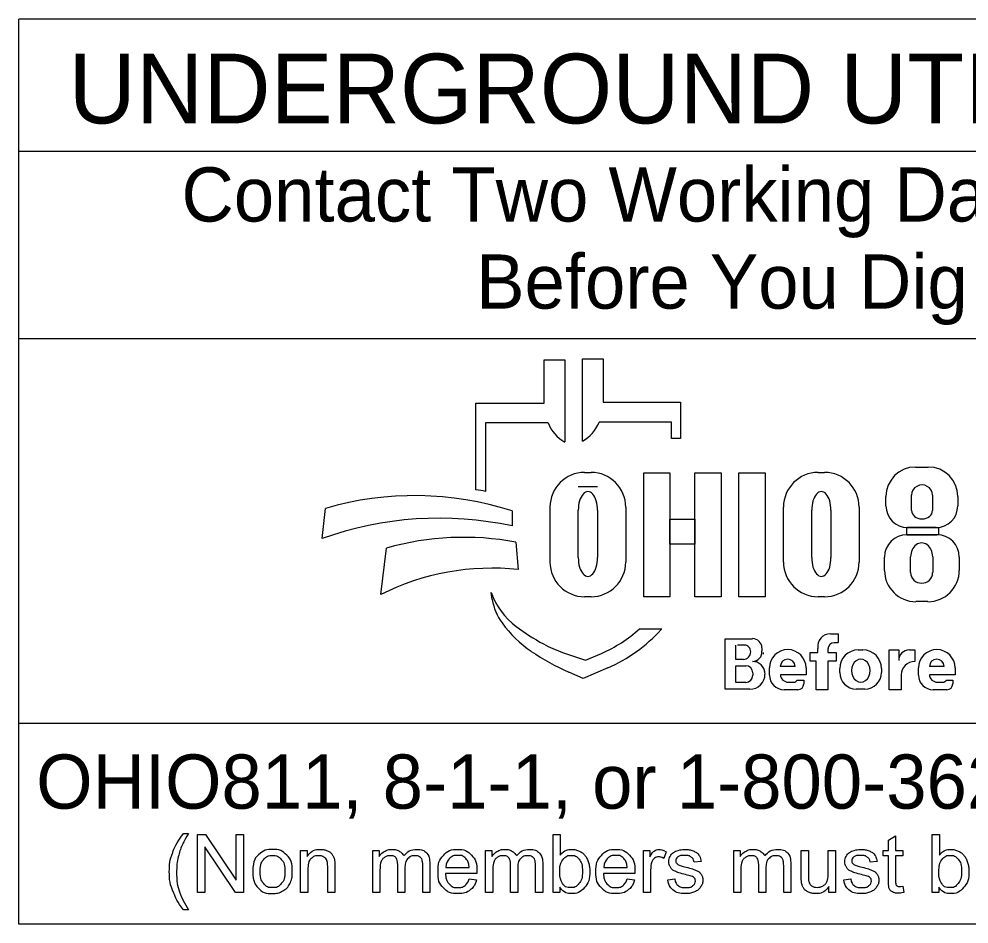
# Model space of a CAD drawing. Extents: x 5.6 to 39.6, y 0.7 to 22.7.
# Drawn here: x 13.593 to 16.047, y 9.658 to 11.996 of the extents above; entities that cross this region are included whole.
import ezdxf

# ---------------------------------------------------------------- set-up
doc = ezdxf.new("R2010")
doc.units = 0
doc.layers.add('SH_Data', color=7, linetype='Continuous')
doc.layers.add('SH_Text', color=7, linetype='Continuous')

msp = doc.modelspace()

# ---------------------------------------------------------------- linework, layer by layer
at = {"layer": 'SH_Data'}
for p, q in [((13.5934, 9.6584), (13.5934, 11.9959)), ((17.8434, 11.9959), (13.5934, 11.9959)), ((13.5934, 11.6544), (17.8434, 11.6544)), ((13.5934, 11.171), (17.8434, 11.171)), ((17.8434, 10.1763), (13.5934, 10.1763)), ((17.8434, 9.6584), (13.5934, 9.6584))]:
    msp.add_line(p, q, dxfattribs=at)
at = {"layer": 'SH_Text'}
for p, q in [((15.0488, 10.9057), (15.0488, 11.1178)), ((15.0488, 11.1178), (15.1024, 11.1178)), ((15.1024, 11.1178), (15.1024, 11.0063)), ((14.9495, 11.004), (14.9495, 11.1154)), ((14.9495, 11.1154), (15.0031, 11.1154)), ((15.0031, 11.1154), (15.0031, 10.9034)), ((14.7735, 10.7801), (14.7735, 11.004)), ((14.7735, 11.004), (14.9495, 11.004)), ((15.1024, 11.0063), (15.3017, 11.0063)), ((15.3017, 11.0063), (15.3017, 10.9125)), ((14.7987, 10.9525), (14.7987, 10.7757)), ((14.9599, 10.9525), (14.7987, 10.9525)), ((15.2784, 10.9548), (15.092, 10.9548)), ((15.2784, 10.9125), (15.2784, 10.9548)), ((15.3017, 10.9125), (15.2784, 10.9125)), ((15.0544, 10.8248), (15.071, 10.8248)), ((15.6575, 10.8248), (15.674, 10.8248)), ((15.909, 10.8388), (15.9418, 10.8388)), ((15.0877, 10.7878), (15.0379, 10.7878)), ((15.8327, 10.7382), (15.8327, 10.7625)), ((15.8989, 10.7268), (15.8989, 10.7661)), ((15.953, 10.7661), (15.953, 10.7268)), ((16.0181, 10.7625), (16.0181, 10.7382)), ((14.3761, 10.6538), (14.3855, 10.7319)), ((14.8668, 10.7254), (14.8668, 10.6866)), ((14.965, 10.5933), (14.965, 10.7353)), ((15.0379, 10.6047), (15.0379, 10.727)), ((15.0877, 10.727), (15.0877, 10.6047)), ((15.1605, 10.7353), (15.1605, 10.5933)), ((15.568, 10.5933), (15.568, 10.7353)), ((15.6409, 10.6047), (15.6409, 10.727)), ((15.6907, 10.727), (15.6907, 10.6047)), ((15.7635, 10.7353), (15.7635, 10.5933)), ((15.9621, 10.6822), (15.8887, 10.6822)), ((15.8869, 10.6639), (15.9642, 10.6639)), ((14.528, 10.5092), (14.5426, 10.6294)), ((14.8768, 10.6448), (14.883, 10.5738)), ((15.829, 10.5719), (15.829, 10.606)), ((15.8965, 10.566), (15.8965, 10.6069)), ((15.9534, 10.6069), (15.9534, 10.566)), ((16.0221, 10.606), (16.0221, 10.5719)), ((14.8157, 10.4963), (14.8126, 10.5143)), ((15.071, 10.5038), (15.0544, 10.5038)), ((15.674, 10.5038), (15.6575, 10.5038)), ((15.9412, 10.491), (15.91, 10.491)), ((15.1959, 10.4205), (15.2534, 10.4205)), ((15.6898, 10.4082), (15.7093, 10.4082)), ((15.7093, 10.4082), (15.7093, 10.3852)), ((15.4172, 10.2647), (15.4172, 10.3954)), ((15.4172, 10.3954), (15.4884, 10.3954)), ((15.7093, 10.3848), (15.6991, 10.3848)), ((14.9975, 10.3601), (15.0569, 10.3396)), ((15.0569, 10.3396), (15.098, 10.3574)), ((15.4452, 10.3419), (15.4452, 10.3789)), ((15.4704, 10.3789), (15.4491, 10.3789)), ((15.5122, 10.3717), (15.5122, 10.3638)), ((15.6372, 10.3369), (15.6372, 10.3598)), ((15.6372, 10.3598), (15.6565, 10.3598)), ((15.6565, 10.3598), (15.6565, 10.3703)), ((15.6826, 10.3683), (15.6826, 10.3598)), ((15.6826, 10.3598), (15.7042, 10.3598)), ((15.7042, 10.3598), (15.7042, 10.3369)), ((15.761, 10.3664), (15.7732, 10.3664)), ((15.8413, 10.2635), (15.8413, 10.3662)), ((15.8413, 10.3662), (15.8658, 10.3662)), ((15.8658, 10.3662), (15.8658, 10.3393)), ((15.8931, 10.3662), (15.907, 10.3662)), ((15.907, 10.3662), (15.907, 10.3365)), ((15.4646, 10.3419), (15.4452, 10.3419)), ((15.6521, 10.3369), (15.6372, 10.3369)), ((15.6521, 10.2635), (15.6521, 10.3369)), ((15.7042, 10.3369), (15.6826, 10.3369)), ((15.6826, 10.3369), (15.6826, 10.2635)), ((15.0509, 10.2926), (15.0136, 10.309)), ((15.1142, 10.32), (15.0509, 10.2926)), ((15.4452, 10.2825), (15.4452, 10.3254)), ((15.4452, 10.3254), (15.4707, 10.3254)), ((15.4889, 10.3073), (15.4889, 10.3009)), ((15.5318, 10.3015), (15.5318, 10.3199)), ((15.5984, 10.3239), (15.5598, 10.3239)), ((15.6263, 10.3199), (15.6263, 10.3022)), ((15.7132, 10.3078), (15.7132, 10.3186)), ((15.821, 10.3186), (15.821, 10.3078)), ((15.9167, 10.3015), (15.9167, 10.3199)), ((15.9833, 10.3239), (15.9448, 10.3239)), ((16.0112, 10.3199), (16.0112, 10.3022)), ((15.4705, 10.2825), (15.4452, 10.2825)), ((15.5202, 10.3044), (15.5202, 10.304)), ((15.6263, 10.3022), (15.5599, 10.3022)), ((15.5808, 10.283), (15.5949, 10.283)), ((15.6035, 10.2885), (15.6204, 10.2885)), ((15.6204, 10.2885), (15.6204, 10.2787)), ((15.8718, 10.3016), (15.8718, 10.2635)), ((16.0112, 10.3022), (15.9448, 10.3022)), ((15.9657, 10.283), (15.9799, 10.283)), ((15.9884, 10.2885), (16.0053, 10.2885)), ((16.0053, 10.2885), (16.0053, 10.2787)), ((15.4809, 10.2647), (15.4172, 10.2647)), ((15.6051, 10.2635), (15.5698, 10.2635)), ((15.6826, 10.2635), (15.6521, 10.2635)), ((15.7782, 10.265), (15.756, 10.265)), ((15.8718, 10.2635), (15.8413, 10.2635)), ((15.9901, 10.2635), (15.9547, 10.2635))]:
    msp.add_line(p, q, dxfattribs=at)
for points in [[(15.2069, 10.8237), (15.2748, 10.8237), (15.2748, 10.5037), (15.2069, 10.5037)], [(15.339, 10.8237), (15.407, 10.8237), (15.407, 10.5037), (15.339, 10.5037)], [(15.4523, 10.8237), (15.5211, 10.8237), (15.5211, 10.5037), (15.4523, 10.5037)], [(15.2748, 10.7038), (15.339, 10.7038), (15.339, 10.6398), (15.2748, 10.6398)], [(15.8866, 10.6822), (15.9682, 10.6822), (15.9682, 10.6637), (15.8866, 10.6637)]]:
    msp.add_lwpolyline(points, close=True, dxfattribs=at)
for points in [[(14.018, 9.8922), (14.0312, 9.8922)], [(14.0548, 9.7396), (14.0548, 9.8897), (14.0751, 9.8897), (14.1541, 9.7718), (14.1541, 9.8897), (14.1731, 9.8897), (14.1731, 9.7396), (14.1528, 9.7396), (14.0738, 9.8575), (14.0738, 9.7396), (14.0548, 9.7396)], [(14.9902, 9.7396), (14.9732, 9.7396), (14.9732, 9.8897), (14.9916, 9.8897), (14.9916, 9.8362)], [(15.9693, 9.7396), (15.9523, 9.7396), (15.9523, 9.8897), (15.9707, 9.8897), (15.9707, 9.8362)], [(15.8392, 9.7714), (15.8392, 9.8341), (15.8256, 9.8341), (15.8256, 9.8484), (15.8392, 9.8484), (15.8392, 9.8754), (15.8576, 9.8864), (15.8576, 9.8484), (15.876, 9.8484), (15.876, 9.8341), (15.8576, 9.8341), (15.8576, 9.7703)], [(14.3207, 9.7396), (14.3207, 9.8484), (14.3373, 9.8484), (14.3373, 9.8329)], [(14.5072, 9.7396), (14.5072, 9.8484), (14.5236, 9.8484), (14.5236, 9.8331)], [(14.7985, 9.7396), (14.7985, 9.8484), (14.815, 9.8484), (14.815, 9.8331)], [(15.2063, 9.7396), (15.2063, 9.8484), (15.2229, 9.8484), (15.2229, 9.8319)], [(15.2654, 9.8449), (15.2589, 9.8279)], [(15.4395, 9.7396), (15.4395, 9.8484), (15.456, 9.8484), (15.456, 9.8331)], [(15.6138, 9.781), (15.6138, 9.8484), (15.6323, 9.8484), (15.6323, 9.7881)], [(15.6835, 9.7901), (15.6835, 9.8484), (15.702, 9.8484), (15.702, 9.7396), (15.6855, 9.7396)], [(15.3553, 9.8203), (15.3372, 9.8179)], [(15.8099, 9.8203), (15.7918, 9.8179)], [(14.3392, 9.799), (14.3392, 9.7396), (14.3207, 9.7396)], [(14.4091, 9.8065), (14.4091, 9.7396), (14.3907, 9.7396), (14.3907, 9.8057)], [(14.5256, 9.796), (14.5256, 9.7396), (14.5072, 9.7396)], [(14.5902, 9.8027), (14.5902, 9.7396), (14.5718, 9.7396), (14.5718, 9.8102)], [(14.6547, 9.8142), (14.6547, 9.7396), (14.6362, 9.7396), (14.6362, 9.8081)], [(14.6958, 9.8044), (14.7565, 9.8044)], [(14.817, 9.796), (14.817, 9.7396), (14.7985, 9.7396)], [(14.8816, 9.8027), (14.8816, 9.7396), (14.8632, 9.7396), (14.8632, 9.8102)], [(14.946, 9.8142), (14.946, 9.7396), (14.9276, 9.7396), (14.9276, 9.8081)], [(15.1038, 9.8044), (15.1645, 9.8044)], [(15.2247, 9.7966), (15.2247, 9.7396), (15.2063, 9.7396)], [(15.458, 9.796), (15.458, 9.7396), (15.4395, 9.7396)], [(15.5226, 9.8027), (15.5226, 9.7396), (15.5042, 9.7396), (15.5042, 9.8102)], [(15.587, 9.8142), (15.587, 9.7396), (15.5686, 9.7396), (15.5686, 9.8081)], [(14.7759, 9.7892), (14.6947, 9.7892)], [(14.7563, 9.7747), (14.7754, 9.7723)], [(15.1839, 9.7892), (15.1027, 9.7892)], [(15.1643, 9.7747), (15.1834, 9.7723)], [(15.2689, 9.7721), (15.2871, 9.7749)], [(15.7235, 9.7721), (15.7417, 9.7749)], [(14.9902, 9.7532), (14.9902, 9.7396)], [(15.6855, 9.7396), (15.6855, 9.7556)], [(15.876, 9.756), (15.8787, 9.7397)], [(15.9693, 9.7532), (15.9693, 9.7396)], [(14.0312, 9.6954), (14.018, 9.6954)]]:
    msp.add_lwpolyline(points, dxfattribs=at)
for centre, radius, start, end in [((15.0512, 10.9893), 0.0985, 201.9296, 240.7469), ((15.0006, 10.9916), 0.0985, 299.2531, 338.0704), ((15.0544, 10.7353), 0.0895, 90, 180), ((15.071, 10.7353), 0.0895, 0, 90), ((15.6575, 10.7353), 0.0895, 90, 180), ((15.674, 10.7353), 0.0895, 0, 90), ((15.909, 10.7625), 0.0763, 90, 180), ((15.9418, 10.7625), 0.0763, 0, 90), ((14.6454, 9.9711), 0.8191, 79.2074, 81.0007), ((14.6156, 9.9458), 0.8191, 72.1402, 106.3144), ((15.8887, 10.7382), 0.056, 180, 270), ((15.9621, 10.7382), 0.056, 270, 0), ((14.6787, 9.8147), 0.8919, 77.8238, 109.8274), ((14.7426, 9.925), 0.7322, 79.44, 105.8467), ((15.8869, 10.606), 0.0579, 90, 180), ((15.9642, 10.606), 0.0579, 0, 90), ((14.8146, 9.9418), 0.6357, 83.8248, 116.8021), ((15.0544, 10.5933), 0.0895, 180, 270), ((15.071, 10.5933), 0.0895, 270, 0), ((15.6575, 10.5933), 0.0895, 180, 270), ((15.674, 10.5933), 0.0895, 270, 0), ((15.91, 10.5719), 0.081, 180, 270), ((15.9412, 10.5719), 0.081, 270, 0), ((15, 10.5864), 0.2008, 201.0457, 232.5314), ((14.957, 10.5204), 0.1433, 189.6817, 216.0884), ((15.0906, 10.6179), 0.3088, 216.0884, 235.7167), ((15.1925, 10.8376), 0.5173, 232.5314, 241.794), ((14.9546, 10.6879), 0.3602, 293.4582, 312.0712), ((14.9546, 10.6879), 0.401, 293.4582, 317.8286), ((15.6898, 10.3747), 0.0335, 90, 187.5187), ((15.1073, 10.6788), 0.3371, 241.794, 250.9821), ((15.4884, 10.3717), 0.0238, 0, 90), ((15.6991, 10.3683), 0.0165, 90, 180), ((15.2571, 10.8621), 0.6044, 235.7167, 246.2325), ((15.4646, 10.3607), 0.0187, 270, 2.0582), ((15.4665, 10.362), 0.0169, 357.8325, 90), ((15.488, 10.3609), 0.0243, 270, 6.6529), ((15.4986, 10.3595), 0.0175, 347.4023, 0), ((15.579, 10.3199), 0.0473, 0, 180), ((15.761, 10.3186), 0.0478, 90, 180), ((15.7732, 10.3186), 0.0478, 0, 90), ((15.8927, 10.3393), 0.0269, 89.2449, 180), ((15.964, 10.3199), 0.0473, 0, 180), ((15.4881, 10.3045), 0.0321, 4.0748, 90), ((15.5791, 10.3229), 0.0193, 2.9632, 177.0368), ((15.9067, 10.3016), 0.0349, 89.6033, 180), ((15.964, 10.3229), 0.0193, 2.9632, 177.0368), ((15.4707, 10.3073), 0.0181, 0, 90), ((15.4873, 10.3044), 0.033, 0, 11.7502), ((15.756, 10.3078), 0.0428, 180, 270), ((15.7782, 10.3078), 0.0428, 270, 0), ((15.4705, 10.3009), 0.0184, 270, 0), ((15.4809, 10.304), 0.0393, 270, 0), ((15.5698, 10.3015), 0.038, 180, 270), ((15.5808, 10.304), 0.021, 184.827, 270), ((15.5949, 10.2924), 0.00938, 270, 335.9979), ((15.9547, 10.3015), 0.038, 180, 270), ((15.9657, 10.304), 0.021, 184.827, 270), ((15.9799, 10.2924), 0.00938, 270, 335.9979), ((15.6051, 10.2787), 0.0152, 270, 0), ((15.9901, 10.2787), 0.0152, 270, 0)]:
    msp.add_arc(centre, radius, start, end, dxfattribs=at)
for centre, major_axis, ratio, start_param, end_param in [((15.0628, 10.727), (0, 0.0484), 0.514403, 4.712389, 7.853982), ((15.6658, 10.727), (0, 0.0484), 0.514403, 4.712389, 7.853982), ((15.9259, 10.7661), (0.0271, 0), 0.969373, 0, 3.141593), ((15.9259, 10.7268), (0.0271, 0), 0.818453, 3.141593, 6.283185), ((15.9249, 10.6069), (0, 0.0358), 0.794529, 4.712389, 7.853982), ((15.0628, 10.6047), (0, 0.0484), 0.514403, 1.570796, 4.712389), ((15.6658, 10.6047), (0, 0.0484), 0.514403, 1.570796, 4.712389), ((15.9249, 10.566), (0.0284, 0), 0.959837, 3.141593, 6.283185), ((15.7676, 10.3132), (0, 0.029), 0.832186, 4.712389, 7.853982), ((15.7676, 10.3132), (0, 0.0302), 0.797287, 1.570796, 4.712389)]:
    msp.add_ellipse(centre, major_axis=major_axis, ratio=ratio, start_param=start_param, end_param=end_param, dxfattribs=at)
for points in [[(14.018, 9.6954), (14.0028, 9.7147), (13.9922, 9.7405), (13.9817, 9.7663), (13.9817, 9.7939), (13.9817, 9.8183), (13.9895, 9.8406), (13.9988, 9.8665), (14.018, 9.8922)], [(14.0312, 9.8922), (14.0188, 9.8709), (14.0149, 9.8618), (14.0086, 9.8477), (14.005, 9.8323), (14.0006, 9.8132), (14.0006, 9.7938), (14.0006, 9.7446), (14.0312, 9.6954)], [(14.1973, 9.794), (14.1973, 9.8242), (14.2141, 9.8387), (14.2281, 9.8508), (14.2482, 9.8508), (14.2707, 9.8508), (14.2849, 9.8361), (14.2991, 9.8214), (14.2991, 9.7955), (14.2991, 9.7745), (14.2928, 9.7625), (14.2865, 9.7505), (14.2745, 9.7438), (14.2625, 9.7372), (14.2482, 9.7372), (14.2254, 9.7372), (14.2113, 9.7518), (14.1973, 9.7665), (14.1973, 9.794)], [(14.3373, 9.8329), (14.3493, 9.8508), (14.3719, 9.8508), (14.3818, 9.8508), (14.39, 9.8473), (14.3982, 9.8437), (14.4023, 9.838), (14.4064, 9.8323), (14.4081, 9.8244), (14.4091, 9.8193), (14.4091, 9.8065)], [(14.5236, 9.8331), (14.5288, 9.8411), (14.5373, 9.8459), (14.5458, 9.8508), (14.5566, 9.8508), (14.5687, 9.8508), (14.5765, 9.8458), (14.5842, 9.8408), (14.5874, 9.8317), (14.6003, 9.8508), (14.621, 9.8508), (14.6372, 9.8508), (14.646, 9.8419), (14.6547, 9.8329), (14.6547, 9.8142)], [(14.7754, 9.7723), (14.7709, 9.7556), (14.7587, 9.7464), (14.7465, 9.7372), (14.7276, 9.7372), (14.7037, 9.7372), (14.6897, 9.7519), (14.6758, 9.7666), (14.6758, 9.7931), (14.6758, 9.8205), (14.6899, 9.8357), (14.704, 9.8508), (14.7265, 9.8508), (14.7484, 9.8508), (14.7622, 9.836), (14.776, 9.8211), (14.776, 9.7942), (14.776, 9.7925), (14.7759, 9.7892)], [(14.815, 9.8331), (14.8201, 9.8411), (14.8286, 9.8459), (14.8371, 9.8508), (14.848, 9.8508), (14.8601, 9.8508), (14.8678, 9.8458), (14.8756, 9.8408), (14.8788, 9.8317), (14.8917, 9.8508), (14.9124, 9.8508), (14.9286, 9.8508), (14.9373, 9.8419), (14.946, 9.8329), (14.946, 9.8142)], [(14.9916, 9.8362), (15.0033, 9.8508), (15.0214, 9.8508), (15.0314, 9.8508), (15.0404, 9.8468), (15.0494, 9.8427), (15.0552, 9.8354), (15.0609, 9.8281), (15.0642, 9.8177), (15.0675, 9.8074), (15.0675, 9.7956), (15.0675, 9.7677), (15.0537, 9.7524), (15.0398, 9.7372), (15.0205, 9.7372), (15.0012, 9.7372), (14.9902, 9.7532)], [(15.1834, 9.7723), (15.1789, 9.7556), (15.1667, 9.7464), (15.1545, 9.7372), (15.1356, 9.7372), (15.1117, 9.7372), (15.0977, 9.7519), (15.0837, 9.7666), (15.0837, 9.7931), (15.0837, 9.8205), (15.0979, 9.8357), (15.112, 9.8508), (15.1345, 9.8508), (15.1563, 9.8508), (15.1702, 9.836), (15.184, 9.8211), (15.184, 9.7942), (15.184, 9.7925), (15.1839, 9.7892)], [(15.2229, 9.8319), (15.2292, 9.8435), (15.2346, 9.8471), (15.24, 9.8508), (15.2464, 9.8508), (15.2557, 9.8508), (15.2654, 9.8449)], [(15.2871, 9.7749), (15.2887, 9.764), (15.2957, 9.7581), (15.3027, 9.7523), (15.3154, 9.7523), (15.3281, 9.7523), (15.3343, 9.7575), (15.3404, 9.7626), (15.3404, 9.7696), (15.3404, 9.7759), (15.335, 9.7795), (15.3312, 9.7819), (15.3161, 9.7857), (15.2958, 9.7908), (15.288, 9.7946), (15.2801, 9.7983), (15.2761, 9.8049), (15.272, 9.8115), (15.272, 9.8195), (15.272, 9.8268), (15.2753, 9.833), (15.2787, 9.8391), (15.2844, 9.8432), (15.2887, 9.8464), (15.2962, 9.8486), (15.3036, 9.8508), (15.3121, 9.8508), (15.3249, 9.8508), (15.3346, 9.8471), (15.3443, 9.8434), (15.349, 9.8371), (15.3536, 9.8308), (15.3553, 9.8203)], [(15.456, 9.8331), (15.4611, 9.8411), (15.4696, 9.8459), (15.4781, 9.8508), (15.489, 9.8508), (15.5011, 9.8508), (15.5088, 9.8458), (15.5166, 9.8408), (15.5197, 9.8317), (15.5327, 9.8508), (15.5534, 9.8508), (15.5696, 9.8508), (15.5783, 9.8419), (15.587, 9.8329), (15.587, 9.8142)], [(15.7417, 9.7749), (15.7432, 9.764), (15.7503, 9.7581), (15.7573, 9.7523), (15.7699, 9.7523), (15.7827, 9.7523), (15.7888, 9.7575), (15.795, 9.7626), (15.795, 9.7696), (15.795, 9.7759), (15.7896, 9.7795), (15.7858, 9.7819), (15.7707, 9.7857), (15.7504, 9.7908), (15.7425, 9.7946), (15.7347, 9.7983), (15.7306, 9.8049), (15.7266, 9.8115), (15.7266, 9.8195), (15.7266, 9.8268), (15.7299, 9.833), (15.7332, 9.8391), (15.739, 9.8432), (15.7433, 9.8464), (15.7507, 9.8486), (15.7582, 9.8508), (15.7667, 9.8508), (15.7795, 9.8508), (15.7892, 9.8471), (15.7989, 9.8434), (15.8035, 9.8371), (15.8081, 9.8308), (15.8099, 9.8203)], [(15.9707, 9.8362), (15.9824, 9.8508), (16.0005, 9.8508), (16.0105, 9.8508), (16.0195, 9.8468), (16.0284, 9.8427), (16.0342, 9.8354), (16.04, 9.8281), (16.0433, 9.8177), (16.0466, 9.8074), (16.0466, 9.7956), (16.0466, 9.7677), (16.0327, 9.7524), (16.0189, 9.7372), (15.9995, 9.7372), (15.9803, 9.7372), (15.9693, 9.7532)], [(14.2163, 9.794), (14.2163, 9.7731), (14.2254, 9.7627), (14.2344, 9.7523), (14.2482, 9.7523), (14.2619, 9.7523), (14.271, 9.7627), (14.2801, 9.7732), (14.2801, 9.7946), (14.2801, 9.8148), (14.271, 9.8252), (14.2618, 9.8356), (14.2482, 9.8356), (14.2344, 9.8356), (14.2254, 9.8252), (14.2163, 9.8149), (14.2163, 9.794)], [(14.3907, 9.8057), (14.3907, 9.817), (14.3885, 9.8226), (14.3864, 9.8281), (14.3809, 9.8315), (14.3754, 9.8348), (14.368, 9.8348), (14.3563, 9.8348), (14.3477, 9.8273), (14.3392, 9.8198), (14.3392, 9.799)], [(14.5718, 9.8102), (14.5718, 9.8225), (14.5673, 9.8287), (14.5628, 9.8348), (14.5525, 9.8348), (14.5448, 9.8348), (14.5381, 9.8307), (14.5315, 9.8266), (14.5286, 9.8187), (14.5256, 9.8108), (14.5256, 9.796)], [(14.6362, 9.8081), (14.6362, 9.8191), (14.6345, 9.824), (14.6327, 9.8289), (14.6279, 9.8318), (14.6232, 9.8348), (14.6169, 9.8348), (14.6054, 9.8348), (14.5978, 9.8272), (14.5902, 9.8195), (14.5902, 9.8027)], [(14.7565, 9.8044), (14.7553, 9.8181), (14.7496, 9.825), (14.7408, 9.8357), (14.7267, 9.8357), (14.714, 9.8357), (14.7054, 9.8272), (14.6967, 9.8186), (14.6958, 9.8044)], [(14.8632, 9.8102), (14.8632, 9.8225), (14.8587, 9.8287), (14.8542, 9.8348), (14.8439, 9.8348), (14.8361, 9.8348), (14.8295, 9.8307), (14.8229, 9.8266), (14.8199, 9.8187), (14.817, 9.8108), (14.817, 9.796)], [(14.9276, 9.8081), (14.9276, 9.8191), (14.9258, 9.824), (14.924, 9.8289), (14.9193, 9.8318), (14.9146, 9.8348), (14.9083, 9.8348), (14.8968, 9.8348), (14.8892, 9.8272), (14.8816, 9.8195), (14.8816, 9.8027)], [(14.99, 9.7948), (14.99, 9.7752), (14.9953, 9.7665), (15.004, 9.7523), (15.0188, 9.7523), (15.0309, 9.7523), (15.0397, 9.7628), (15.0485, 9.7733), (15.0485, 9.7941), (15.0485, 9.8154), (15.0401, 9.8256), (15.0316, 9.8357), (15.0197, 9.8357), (15.0076, 9.8357), (14.9988, 9.8252), (14.99, 9.8147), (14.99, 9.7948)], [(15.1645, 9.8044), (15.1633, 9.8181), (15.1576, 9.825), (15.1488, 9.8357), (15.1347, 9.8357), (15.122, 9.8357), (15.1134, 9.8272), (15.1047, 9.8186), (15.1038, 9.8044)], [(15.2589, 9.8279), (15.2522, 9.8318), (15.2455, 9.8318), (15.2394, 9.8318), (15.2346, 9.8282), (15.2299, 9.8245), (15.2278, 9.8181), (15.2247, 9.8082), (15.2247, 9.7966)], [(15.3372, 9.8179), (15.336, 9.8263), (15.3301, 9.831), (15.3242, 9.8357), (15.3134, 9.8357), (15.3007, 9.8357), (15.2953, 9.8315), (15.2899, 9.8273), (15.2899, 9.8217), (15.2899, 9.8181), (15.2921, 9.8152), (15.2944, 9.8122), (15.2992, 9.8103), (15.302, 9.8092), (15.3155, 9.8055), (15.3351, 9.8003), (15.3428, 9.797), (15.3506, 9.7937), (15.355, 9.7873), (15.3594, 9.781), (15.3594, 9.7716), (15.3594, 9.7624), (15.354, 9.7542), (15.3487, 9.7461), (15.3385, 9.7416), (15.3283, 9.7372), (15.3155, 9.7372), (15.2943, 9.7372), (15.2831, 9.746), (15.272, 9.7548), (15.2689, 9.7721)], [(15.5042, 9.8102), (15.5042, 9.8225), (15.4997, 9.8287), (15.4952, 9.8348), (15.4849, 9.8348), (15.4771, 9.8348), (15.4705, 9.8307), (15.4639, 9.8266), (15.4609, 9.8187), (15.458, 9.8108), (15.458, 9.796)], [(15.5686, 9.8081), (15.5686, 9.8191), (15.5668, 9.824), (15.565, 9.8289), (15.5603, 9.8318), (15.5556, 9.8348), (15.5493, 9.8348), (15.5378, 9.8348), (15.5302, 9.8272), (15.5226, 9.8195), (15.5226, 9.8027)], [(15.7918, 9.8179), (15.7906, 9.8263), (15.7847, 9.831), (15.7788, 9.8357), (15.768, 9.8357), (15.7553, 9.8357), (15.7499, 9.8315), (15.7444, 9.8273), (15.7444, 9.8217), (15.7444, 9.8181), (15.7467, 9.8152), (15.7489, 9.8122), (15.7538, 9.8103), (15.7565, 9.8092), (15.7701, 9.8055), (15.7897, 9.8003), (15.7974, 9.797), (15.8052, 9.7937), (15.8096, 9.7873), (15.814, 9.781), (15.814, 9.7716), (15.814, 9.7624), (15.8086, 9.7542), (15.8032, 9.7461), (15.7931, 9.7416), (15.7829, 9.7372), (15.7701, 9.7372), (15.7488, 9.7372), (15.7377, 9.746), (15.7266, 9.7548), (15.7235, 9.7721)], [(15.9691, 9.7948), (15.9691, 9.7752), (15.9744, 9.7665), (15.9831, 9.7523), (15.9979, 9.7523), (16.01, 9.7523), (16.0188, 9.7628), (16.0276, 9.7733), (16.0276, 9.7941), (16.0276, 9.8154), (16.0191, 9.8256), (16.0107, 9.8357), (15.9987, 9.8357), (15.9867, 9.8357), (15.9779, 9.8252), (15.9691, 9.8147), (15.9691, 9.7948)], [(14.6947, 9.7892), (14.6958, 9.7713), (14.7049, 9.7618), (14.714, 9.7523), (14.7276, 9.7523), (14.7378, 9.7523), (14.745, 9.7576), (14.7521, 9.763), (14.7563, 9.7747)], [(15.1027, 9.7892), (15.1038, 9.7713), (15.1129, 9.7618), (15.122, 9.7523), (15.1356, 9.7523), (15.1458, 9.7523), (15.153, 9.7576), (15.1601, 9.763), (15.1643, 9.7747)], [(15.6855, 9.7556), (15.6728, 9.7372), (15.651, 9.7372), (15.6414, 9.7372), (15.633, 9.7409), (15.6247, 9.7445), (15.6207, 9.7501), (15.6166, 9.7557), (15.615, 9.7638), (15.6138, 9.7692), (15.6138, 9.781)], [(15.6323, 9.7881), (15.6323, 9.7737), (15.6334, 9.7686), (15.6351, 9.7614), (15.6408, 9.7572), (15.6464, 9.7531), (15.6547, 9.7531), (15.663, 9.7531), (15.6702, 9.7573), (15.6775, 9.7616), (15.6805, 9.7689), (15.6835, 9.7762), (15.6835, 9.7901)], [(15.8787, 9.7397), (15.8709, 9.7381), (15.8648, 9.7381), (15.8547, 9.7381), (15.8492, 9.7413), (15.8437, 9.7444), (15.8414, 9.7496), (15.8392, 9.7548), (15.8392, 9.7714)], [(15.8576, 9.7703), (15.8576, 9.7624), (15.8586, 9.7602), (15.8595, 9.7579), (15.8617, 9.7566), (15.8639, 9.7553), (15.868, 9.7553), (15.871, 9.7553), (15.876, 9.756)]]:
    msp.add_open_spline(points, degree=3, dxfattribs=at)

# ---------------------------------------------------------------- texts
for s, height, p in [('UNDERGROUND UTILITIES', 0.18, (13.7216, 11.7263)), ('Contact Two Working Days', 0.14, (14.0131, 11.4728)), ('Before You Dig', 0.14, (14.7743, 11.2478)), ('OHIO811, 8-1-1, or 1-800-362-2764', 0.14, (13.6379, 9.9563))]:
    msp.add_text(s, height=height, dxfattribs=at).set_placement(p)

doc.saveas('drawing.dxf')
